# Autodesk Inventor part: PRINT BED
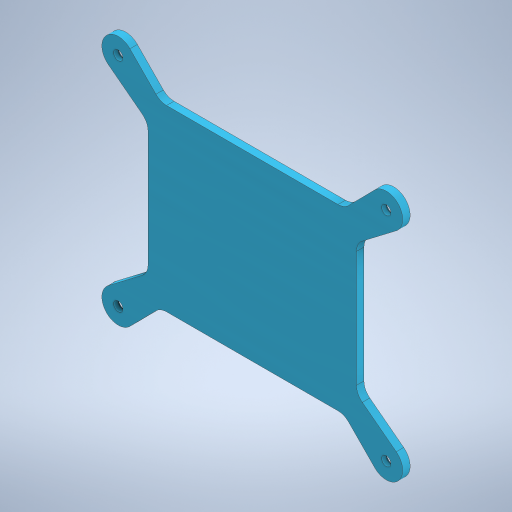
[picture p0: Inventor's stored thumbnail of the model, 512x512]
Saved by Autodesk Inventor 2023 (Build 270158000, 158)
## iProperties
Created: 2025-07
Part Number: PRINT BED
Material: Generic
Document SubType Name: Modeling
Designer: erjon
Density: 1 g/cm^3
Appearance: Default
Author: erjon
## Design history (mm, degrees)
feature "Base1"
body "Solid1"
